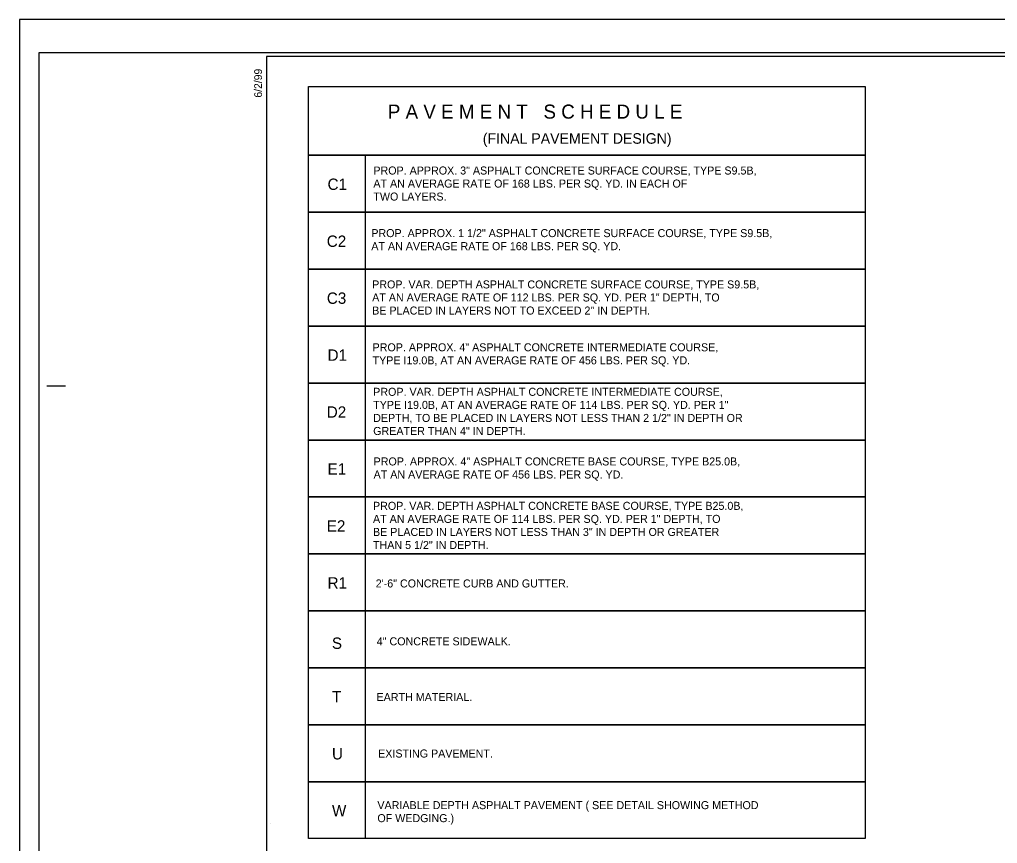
# Model space of a CAD drawing. Extents: x 573786 to 574032, y -53324 to -53148.
# Drawn here: x 573845 to 573911.1, y -53270.1 to -53214.4 of the extents above; entities that cross this region are included whole.
import ezdxf

# ---------------------------------------------------------------- set-up
doc = ezdxf.new("R2010")
doc.units = 0
for name, color, linetype in [('Prop Dimension Text', 7, 'Continuous'), ('Prop Pavement Schedule Description CELL', 7, 'Continuous'), ('Sheet Cutting Line CELL', 7, 'Continuous'), ('Sheet Plot Border Inside CELL', 7, 'Continuous'), ('Sheet Plot Border Outside CELL', 7, 'Continuous'), ('Sheet Typical CELL', 7, 'Continuous')]:
    doc.layers.add(name, color=color, linetype=linetype)

msp = doc.modelspace()

# ---------------------------------------------------------------- linework, layer by layer
at = {"layer": 'Prop Pavement Schedule Description CELL'}
for p, q in [((573864.535, -53265.936), (573864.535, -53262.088)), ((573864.535, -53262.088), (573902.156, -53262.088)), ((573868.383, -53265.936), (573868.383, -53262.088)), ((573902.156, -53262.088), (573902.156, -53265.936)), ((573868.383, -53265.936), (573864.535, -53265.936)), ((573902.156, -53265.936), (573868.383, -53265.936)), ((573861.94, -53268.776), (573861.94, -53268.776))]:
    msp.add_line(p, q, dxfattribs=at)
for points in [[(573864.535, -53222.822), (573864.535, -53222.822), (573864.535, -53218.974), (573902.155, -53218.974), (573902.155, -53223.613), (573864.535, -53223.613), (573864.535, -53218.974)], [(573868.383, -53227.462), (573864.535, -53227.462), (573864.535, -53223.613), (573902.155, -53223.613), (573902.155, -53227.462), (573868.383, -53227.462), (573868.383, -53223.613)], [(573868.383, -53231.309), (573864.535, -53231.309), (573864.535, -53227.461), (573902.155, -53227.461), (573902.155, -53231.309), (573868.383, -53231.309), (573868.383, -53227.461)], [(573868.383, -53235.156), (573864.535, -53235.156), (573864.535, -53231.309), (573902.155, -53231.309), (573902.155, -53235.156), (573868.383, -53235.156), (573868.383, -53231.309)], [(573868.383, -53239.004), (573864.535, -53239.004), (573864.535, -53235.156), (573902.155, -53235.156), (573902.155, -53239.004), (573868.383, -53239.004), (573868.383, -53235.156)], [(573868.383, -53242.851), (573864.535, -53242.851), (573864.535, -53239.004), (573902.156, -53239.004), (573902.156, -53242.851), (573868.383, -53242.851), (573868.383, -53239.004)], [(573868.383, -53246.699), (573864.535, -53246.699), (573864.535, -53242.851), (573902.155, -53242.851), (573902.155, -53246.699), (573868.383, -53246.699), (573868.383, -53242.851)], [(573868.383, -53250.546), (573864.535, -53250.546), (573864.535, -53246.699), (573902.155, -53246.699), (573902.155, -53250.546), (573868.383, -53250.546), (573868.383, -53246.699)], [(573868.383, -53254.394), (573864.535, -53254.394), (573864.535, -53250.546), (573902.156, -53250.546), (573902.156, -53254.394), (573868.383, -53254.394), (573868.383, -53250.546)], [(573868.383, -53258.241), (573864.535, -53258.241), (573864.535, -53254.394), (573902.156, -53254.394), (573902.156, -53258.241), (573868.383, -53258.241), (573868.383, -53254.394)], [(573868.383, -53262.088), (573864.535, -53262.088), (573864.535, -53258.241), (573902.156, -53258.241), (573902.156, -53262.088), (573868.383, -53262.088), (573868.383, -53258.241)], [(573868.383, -53269.783), (573864.535, -53269.783), (573864.535, -53265.936), (573902.156, -53265.936), (573902.156, -53269.783), (573868.383, -53269.783), (573868.383, -53265.936)]]:
    msp.add_lwpolyline(points, dxfattribs=at)
at = {"layer": 'Sheet Cutting Line CELL'}
for p, q in [((574013.401, -53214.447), (573845.001, -53214.447)), ((573845.001, -53214.447), (573845.001, -53324.447))]:
    msp.add_line(p, q, dxfattribs=at)
at = {"layer": 'Sheet Plot Border Inside CELL'}
msp.add_lwpolyline([(574012.951, -53216.692), (573846.301, -53216.692), (573846.301, -53322.202), (574012.951, -53322.202)], close=True, dxfattribs=at)
at = {"layer": 'Sheet Plot Border Outside CELL'}
msp.add_lwpolyline([(574013.401, -53214.447), (573845.001, -53214.447), (573845.001, -53324.447), (574013.401, -53324.447)], close=True, dxfattribs=at)
at = {"layer": 'Sheet Typical CELL'}
msp.add_line((573846.851, -53239.197), (573848.101, -53239.197), dxfattribs=at)
msp.add_lwpolyline([(574011.701, -53216.947), (573861.701, -53216.947), (573861.701, -53321.947), (574011.701, -53321.947)], close=True, dxfattribs=at)

# ---------------------------------------------------------------- texts
at = {"layer": 'Prop Dimension Text'}
for s, height, p in [('P A V E M E N T   S C H E D U L E', 0.95, (573869.889, -53221.141)), ('(FINAL PAVEMENT DESIGN)', 0.7125, (573876.306, -53222.836))]:
    msp.add_text(s, height=height, rotation=0.00231, dxfattribs=at).set_placement(p)
at = {"layer": 'Prop Pavement Schedule Description CELL'}
for s, height, p in [('PROP. APPROX. 3" ASPHALT CONCRETE SURFACE COURSE, TYPE S9.5B, ', 0.54079, (573868.913, -53224.915)), ('C1', 0.7681, (573865.818, -53225.957)), ('AT AN AVERAGE RATE OF 168 LBS. PER SQ. YD. IN EACH OF', 0.54079, (573868.913, -53225.797)), ('TWO LAYERS. ', 0.54079, (573868.913, -53226.676)), ('C2', 0.7681, (573865.764, -53229.804)), ('PROP. APPROX. 1 1/2" ASPHALT CONCRETE SURFACE COURSE, TYPE S9.5B, ', 0.54079, (573868.774, -53229.144)), ('AT AN AVERAGE RATE OF 168 LBS. PER SQ. YD.', 0.54079, (573868.774, -53230.026)), ('PROP. VAR. DEPTH ASPHALT CONCRETE SURFACE COURSE, TYPE S9.5B,', 0.54079, (573868.832, -53232.61)), ('C3', 0.7681, (573865.769, -53233.652)), ('AT AN AVERAGE RATE OF 112 LBS. PER SQ. YD. PER 1" DEPTH, TO', 0.54079, (573868.832, -53233.493)), ('BE PLACED IN LAYERS NOT TO EXCEED 2" IN DEPTH.', 0.54079, (573868.832, -53234.375)), ('PROP. APPROX. 4" ASPHALT CONCRETE INTERMEDIATE COURSE,', 0.54079, (573868.859, -53236.859)), ('D1', 0.7681, (573865.818, -53237.499)), ('TYPE I19.0B, AT AN AVERAGE RATE OF 456 LBS. PER SQ. YD.', 0.54079, (573868.859, -53237.741)), ('PROP. VAR. DEPTH ASPHALT CONCRETE INTERMEDIATE COURSE,', 0.54079, (573868.901, -53239.866)), ('TYPE I19.0B, AT AN AVERAGE RATE OF 114 LBS. PER SQ. YD. PER 1" ', 0.54079, (573868.901, -53240.749)), ('D2', 0.7681, (573865.764, -53241.346)), ('DEPTH, TO BE PLACED IN LAYERS NOT LESS THAN 2 1/2" IN DEPTH OR', 0.54079, (573868.901, -53241.631)), ('GREATER THAN 4" IN DEPTH.', 0.54079, (573868.901, -53242.513)), ('PROP. APPROX. 4" ASPHALT CONCRETE BASE COURSE, TYPE B25.0B,', 0.54079, (573868.929, -53244.57)), ('E1', 0.7681, (573865.818, -53245.195)), ('AT AN AVERAGE RATE OF 456 LBS. PER SQ. YD.', 0.54079, (573868.929, -53245.452)), ('PROP. VAR. DEPTH ASPHALT CONCRETE BASE COURSE, TYPE B25.0B,', 0.54079, (573868.888, -53247.569)), ('AT AN AVERAGE RATE OF 114 LBS. PER SQ. YD. PER 1" DEPTH, TO', 0.54079, (573868.888, -53248.451)), ('E2', 0.7681, (573865.764, -53249.042)), ('BE PLACED IN LAYERS NOT LESS THAN 3" IN DEPTH OR GREATER', 0.54079, (573868.888, -53249.334)), ('THAN 5 1/2" IN DEPTH.', 0.54079, (573868.888, -53250.216)), ('R1', 0.7681, (573865.818, -53252.89)), ('2\'-6" CONCRETE CURB AND GUTTER.', 0.54079, (573869.07, -53252.813)), ('S', 0.768, (573866.11, -53256.963)), ('4" CONCRETE SIDEWALK.', 0.54079, (573869.142, -53256.723)), ('T', 0.768, (573866.116, -53260.584)), ('EARTH MATERIAL.', 0.54079, (573869.127, -53260.487)), ('U', 0.768, (573866.116, -53264.432)), ('EXISTING PAVEMENT.', 0.54079, (573869.233, -53264.303)), ('VARIABLE DEPTH ASPHALT PAVEMENT ( SEE DETAIL SHOWING METHOD', 0.54079, (573869.184, -53267.79)), ('W', 0.768, (573866.116, -53268.279)), ('OF WEDGING.)', 0.54079, (573869.184, -53268.669))]:
    msp.add_text(s, height=height, dxfattribs=at).set_placement(p)
at = {"layer": 'Sheet Typical CELL'}
msp.add_text('6/2/99', height=0.525, rotation=90, dxfattribs=at).set_placement((573861.386, -53219.722))

doc.saveas('drawing.dxf')
